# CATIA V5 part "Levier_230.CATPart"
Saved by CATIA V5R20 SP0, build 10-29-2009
Part number: Levier_230
Bounding box of the stored display mesh (mm): x -20 to 20, y -55 to 205, z -15 to 15
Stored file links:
  C:\Users\Anne\Documents\IFMA\2e année\3e semestre\IAO\Projet\Catia\Levier_230.CATPart
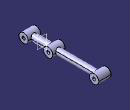
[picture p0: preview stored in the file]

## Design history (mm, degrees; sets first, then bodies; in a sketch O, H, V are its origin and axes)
Parameters
  `Longueur L1` = 80 mm
  `Longueur L2` = 150 mm
  `Largeur La` = 40 mm
  D_Bielle = 20 mm
  D_Trou = 10 mm
  D_Pivot = 30 mm
Body1 (main body)
  Sketch1 on yz-plane, origin (0, 0, 0), H (0, 1, 0), V (0, 0, 1)
    circle A1 centre (40, 0) radius 15
    point P1 (40, 0)
    point P2 (-40, 0)
    circle A2 centre (-40, 0) radius 15
    circle A3 centre (190, 0) radius 15
    point P3 (190, 0)
    radius A1 = 15 {= D_Pivot /2}
    distance P2 P1 = 80 {= `Longueur L1`}
    radius A3 = 15 {= D_Pivot /2}
    distance P1 P3 = 150 {= `Longueur L2`}
    coincidence: P1 H, P3 H
    symmetry: A1 A2 V
  Pad1: profile Sketch1, direction (1, 0, 0), length 20 {= `Largeur La` /2}, mirrored extent
  Sketch2 on zx-plane, origin (0, 0, 0), H (-1, 0, 0), V (0, 0, 1)
    circle A1 centre (0, 0) radius 10
    radius A1 = 10 {= D_Bielle /2}
  Pad2: profile Sketch2, direction (0, 1, 0), length 40 {= `Longueur L1` /2}, mirrored extent
  Sketch3 on xy-plane, origin (0, 0, 0), H (1, 0, 0), V (0, 1, 0)
    line L1 (0, 190) -> (10, 190)
    line L2 (10, 190) -> (10, 40)
    line L3 (10, 40) -> (0, 40)
    line L4 (0, 40) -> (0, 190)
    distance L2 L4 = 10 {= D_Bielle /2}
    distance L3 L1 = 150 {= `Longueur L2`}
    horizontal: L1 H, L3 H
    vertical: L2 V, L4 V
  Shaft1: profile Sketch3, axis Sketch3.L4, angle 360
  Sketch4 on start face of Pad1, origin (-20, -41.4204, -2.1508), H (0, 1, 0), V (0, 0, -1)
    point P1 (1.4204, -2.1508)
    reference projected circle E1 centre (1.4204, -2.1508) radius 15 from edge [start face of Pad1 | face of Pad1 from Sketch1.A2]
    concentricity: P1 E1
  Hole1: placed by Sketch4, at (-20, -40, 0) direction (1, 0, 0), diameter 10 {= D_Trou}, through (limit type 6)
  Sketch5 on start face of Pad1, origin (-20, 41.183, -2.5631), H (0, 1, 0), V (0, 0, -1)
    point P1 (-1.183, -2.5631)
    reference projected circle E1 centre (-1.183, -2.5631) radius 15 from edge [start face of Pad1 | face of Pad1 from Sketch1.A1]
    concentricity: E1 P1
  Hole2: placed by Sketch5, at (-20, 40, 0) direction (1, 0, 0), diameter 10 {= D_Trou}, through (limit type 6)
  Sketch6 on start face of Pad1, origin (-20, 194.14, 1.7201), H (0, 1, 0), V (0, 0, -1)
    point P1 (-4.14, 1.7201)
    reference projected circle E1 centre (-4.14, 1.7201) radius 15 from edge [start face of Pad1 | face of Pad1 from Sketch1.A3]
    concentricity: P1 E1
  Hole3: placed by Sketch6, at (-20, 190, 0) direction (1, 0, 0), diameter 10 {= D_Trou}, through (limit type 6)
